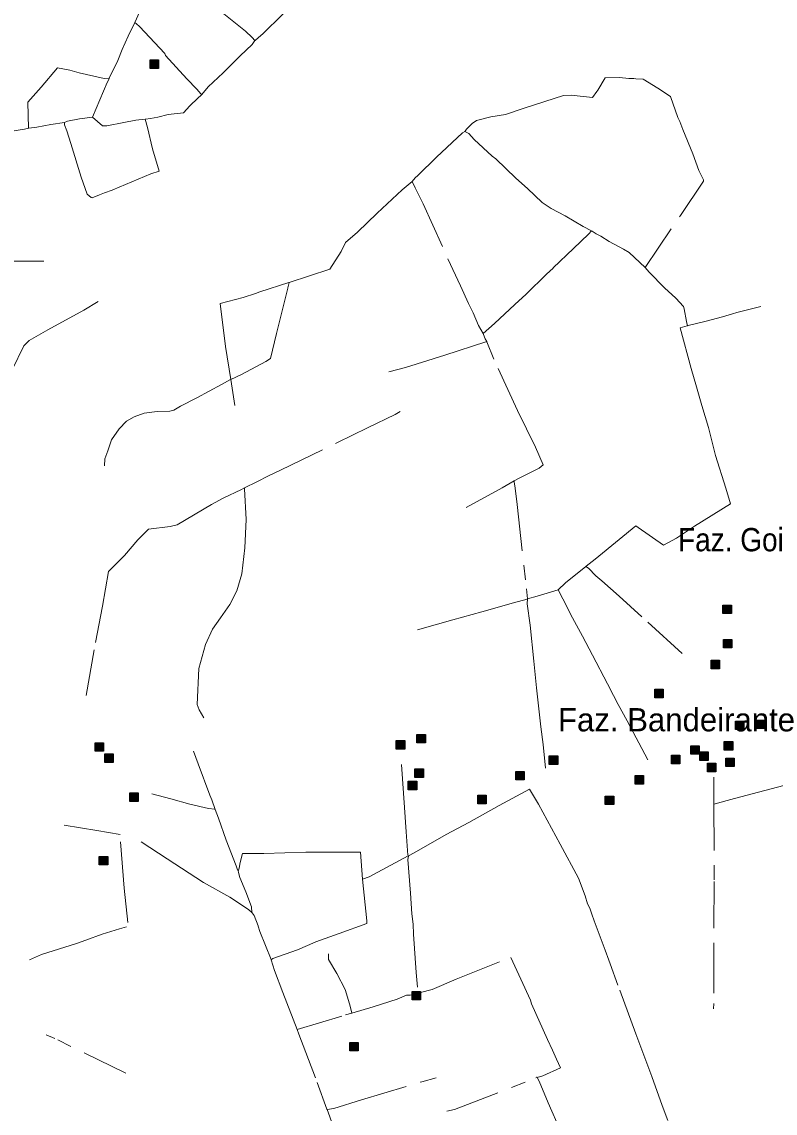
# Model space of a CAD drawing. Extents: x 393.5 to 446.9, y 8064.8 to 8120.4.
# Drawn here: x 407.05 to 412.23, y 8091.17 to 8098.67 of the extents above; entities that cross this region are included whole.
import ezdxf

# ---------------------------------------------------------------- set-up
doc = ezdxf.new("R2010")
doc.units = 0
doc.header["$LTSCALE"] = 0.064
doc.linetypes.add('DOT_DASHED', pattern=[7.7, 5, -1.2, 0.3, -1.2])
doc.layers.add('2', color=7, linetype='Continuous', lineweight=25)
doc.layers.add('22', color=7, linetype='DOT_DASHED', lineweight=13)
doc.layers.add('61', color=7, linetype='Continuous')

msp = doc.modelspace()

# ---------------------------------------------------------------- hatches: boundary and pattern name
at = {"layer": '2'}
for points in [[(407.936, 8098.4084), (407.994, 8098.4084), (407.994, 8098.3504), (407.936, 8098.3504)], [(411.8734, 8094.6626), (411.9314, 8094.6626), (411.9314, 8094.6046), (411.8734, 8094.6046)], [(411.8772, 8094.4259), (411.9352, 8094.4259), (411.9352, 8094.3679), (411.8772, 8094.3679)], [(411.7923, 8094.2825), (411.8503, 8094.2825), (411.8503, 8094.2245), (411.7923, 8094.2245)], [(411.4043, 8094.0837), (411.4623, 8094.0837), (411.4623, 8094.0257), (411.4043, 8094.0257)], [(411.96, 8093.8644), (412.018, 8093.8644), (412.018, 8093.8064), (411.96, 8093.8064)], [(412.1068, 8093.8715), (412.1648, 8093.8715), (412.1648, 8093.8135), (412.1068, 8093.8135)], [(407.5578, 8093.716), (407.6158, 8093.716), (407.6158, 8093.658), (407.5578, 8093.658)], [(409.6277, 8093.7308), (409.6857, 8093.7308), (409.6857, 8093.6728), (409.6277, 8093.6728)], [(409.77, 8093.7728), (409.828, 8093.7728), (409.828, 8093.7148), (409.77, 8093.7148)], [(411.883, 8093.7235), (411.941, 8093.7235), (411.941, 8093.6655), (411.883, 8093.6655)], [(407.6236, 8093.6388), (407.6816, 8093.6388), (407.6816, 8093.5808), (407.6236, 8093.5808)], [(410.6798, 8093.6257), (410.7378, 8093.6257), (410.7378, 8093.5677), (410.6798, 8093.5677)], [(411.5191, 8093.63), (411.5771, 8093.63), (411.5771, 8093.572), (411.5191, 8093.572)], [(411.6521, 8093.6952), (411.7101, 8093.6952), (411.7101, 8093.6372), (411.6521, 8093.6372)], [(411.7151, 8093.6529), (411.7731, 8093.6529), (411.7731, 8093.5949), (411.7151, 8093.5949)], [(411.7667, 8093.5746), (411.8247, 8093.5746), (411.8247, 8093.5166), (411.7667, 8093.5166)], [(411.8939, 8093.6104), (411.9519, 8093.6104), (411.9519, 8093.5524), (411.8939, 8093.5524)], [(409.7558, 8093.5363), (409.8138, 8093.5363), (409.8138, 8093.4783), (409.7558, 8093.4783)], [(410.4488, 8093.5188), (410.5068, 8093.5188), (410.5068, 8093.4608), (410.4488, 8093.4608)], [(411.2698, 8093.4904), (411.3278, 8093.4904), (411.3278, 8093.4324), (411.2698, 8093.4324)], [(409.71, 8093.4512), (409.768, 8093.4512), (409.768, 8093.3932), (409.71, 8093.3932)], [(407.7957, 8093.3708), (407.8537, 8093.3708), (407.8537, 8093.3128), (407.7957, 8093.3128)], [(410.1873, 8093.3551), (410.2453, 8093.3551), (410.2453, 8093.2971), (410.1873, 8093.2971)], [(411.0644, 8093.3499), (411.1224, 8093.3499), (411.1224, 8093.2919), (411.0644, 8093.2919)], [(407.5855, 8092.9343), (407.6435, 8092.9343), (407.6435, 8092.8763), (407.5855, 8092.8763)], [(409.7361, 8092.0072), (409.7941, 8092.0072), (409.7941, 8091.9492), (409.7361, 8091.9492)], [(409.3085, 8091.6564), (409.3665, 8091.6564), (409.3665, 8091.5984), (409.3085, 8091.5984)]]:
    msp.add_hatch(color=256, dxfattribs=at).paths.add_polyline_path(points)

# ---------------------------------------------------------------- linework, layer by layer
for points in [[(407.936, 8098.4084), (407.994, 8098.4084), (407.994, 8098.3504), (407.936, 8098.3504)], [(411.8734, 8094.6626), (411.9314, 8094.6626), (411.9314, 8094.6046), (411.8734, 8094.6046)], [(411.8772, 8094.4259), (411.9352, 8094.4259), (411.9352, 8094.3679), (411.8772, 8094.3679)], [(411.7923, 8094.2825), (411.8503, 8094.2825), (411.8503, 8094.2245), (411.7923, 8094.2245)], [(411.4043, 8094.0837), (411.4623, 8094.0837), (411.4623, 8094.0257), (411.4043, 8094.0257)], [(411.96, 8093.8644), (412.018, 8093.8644), (412.018, 8093.8064), (411.96, 8093.8064)], [(412.1068, 8093.8715), (412.1648, 8093.8715), (412.1648, 8093.8135), (412.1068, 8093.8135)], [(407.5578, 8093.716), (407.6158, 8093.716), (407.6158, 8093.658), (407.5578, 8093.658)], [(409.6277, 8093.7308), (409.6857, 8093.7308), (409.6857, 8093.6728), (409.6277, 8093.6728)], [(409.77, 8093.7728), (409.828, 8093.7728), (409.828, 8093.7148), (409.77, 8093.7148)], [(411.883, 8093.7235), (411.941, 8093.7235), (411.941, 8093.6655), (411.883, 8093.6655)], [(407.6236, 8093.6388), (407.6816, 8093.6388), (407.6816, 8093.5808), (407.6236, 8093.5808)], [(410.6798, 8093.6257), (410.7378, 8093.6257), (410.7378, 8093.5677), (410.6798, 8093.5677)], [(411.5191, 8093.63), (411.5771, 8093.63), (411.5771, 8093.572), (411.5191, 8093.572)], [(411.6521, 8093.6952), (411.7101, 8093.6952), (411.7101, 8093.6372), (411.6521, 8093.6372)], [(411.7151, 8093.6529), (411.7731, 8093.6529), (411.7731, 8093.5949), (411.7151, 8093.5949)], [(411.7667, 8093.5746), (411.8247, 8093.5746), (411.8247, 8093.5166), (411.7667, 8093.5166)], [(411.8939, 8093.6104), (411.9519, 8093.6104), (411.9519, 8093.5524), (411.8939, 8093.5524)], [(409.7558, 8093.5363), (409.8138, 8093.5363), (409.8138, 8093.4783), (409.7558, 8093.4783)], [(410.4488, 8093.5188), (410.5068, 8093.5188), (410.5068, 8093.4608), (410.4488, 8093.4608)], [(411.2698, 8093.4904), (411.3278, 8093.4904), (411.3278, 8093.4324), (411.2698, 8093.4324)], [(409.71, 8093.4512), (409.768, 8093.4512), (409.768, 8093.3932), (409.71, 8093.3932)], [(407.7957, 8093.3708), (407.8537, 8093.3708), (407.8537, 8093.3128), (407.7957, 8093.3128)], [(410.1873, 8093.3551), (410.2453, 8093.3551), (410.2453, 8093.2971), (410.1873, 8093.2971)], [(411.0644, 8093.3499), (411.1224, 8093.3499), (411.1224, 8093.2919), (411.0644, 8093.2919)], [(407.5855, 8092.9343), (407.6435, 8092.9343), (407.6435, 8092.8763), (407.5855, 8092.8763)], [(409.7361, 8092.0072), (409.7941, 8092.0072), (409.7941, 8091.9492), (409.7361, 8091.9492)], [(409.3085, 8091.6564), (409.3665, 8091.6564), (409.3665, 8091.5984), (409.3085, 8091.5984)]]:
    msp.add_lwpolyline(points, close=True, dxfattribs=at)
at = {"layer": '22'}
for p, q in [((407.83, 8098.6664), (407.8406, 8098.6558)), ((407.9006, 8098.0014), (407.9009, 8098.0004)), ((409.7368, 8097.5733), (409.7587, 8097.5284)), ((410.2254, 8096.5273), (410.2274, 8096.5223)), ((409.7746, 8094.4923), (410.0176, 8094.5617)), ((411.8111, 8093.4789), (411.8117, 8093.295)), ((408.383, 8093.2582), (408.4043, 8093.1987)), ((408.6781, 8092.4582), (408.6787, 8092.4564))]:
    msp.add_line(p, q, dxfattribs=at)
for points in [[(407.83, 8098.6664), (408.0233, 8099.0981), (408.0233, 8099.1098), (407.9602, 8099.1529), (407.7401, 8099.3272), (407.4951, 8099.5181), (407.4476, 8099.5602), (407.4457, 8099.5619), (407.4445, 8099.563)], [(408.7258, 8099.347), (408.6856, 8099.3121), (408.4969, 8099.1933), (408.2819, 8099.0588), (408.1823, 8098.989), (408.1631, 8098.9768), (408.1631, 8098.9576), (408.233, 8098.9052), (408.3728, 8098.7812), (408.5912, 8098.6066), (408.6367, 8098.5629), (408.6563, 8098.5415)], [(408.8535, 8099.1468), (408.8833, 8099.0981), (408.9462, 8099.0073), (409.0143, 8098.9025), (409.0004, 8098.878), (408.8448, 8098.7209), (408.7103, 8098.5882), (408.6808, 8098.5624), (408.6569, 8098.542), (408.6563, 8098.5415)], [(407.6545, 8098.282), (407.7122, 8098.4053), (407.7437, 8098.4799), (407.7854, 8098.5709), (407.83, 8098.6664)], [(407.8406, 8098.6558), (407.8618, 8098.6389), (408.036, 8098.4534), (408.041, 8098.4384)], [(408.2897, 8098.1701), (408.3333, 8098.2226), (408.4364, 8098.3204), (408.5552, 8098.4374), (408.6374, 8098.5142), (408.6563, 8098.5415)], [(408.041, 8098.4384), (408.1884, 8098.2782), (408.2553, 8098.2074), (408.2831, 8098.1756), (408.2897, 8098.1701)], [(407.3824, 8098.3373), (407.2988, 8098.354), (407.1865, 8098.2207), (407.0955, 8098.1191), (407.0988, 8097.9388)], [(407.6545, 8098.282), (407.6192, 8098.2808), (407.4464, 8098.319), (407.3824, 8098.3373)], [(407.5396, 8098.0158), (407.6396, 8098.2524), (407.6528, 8098.2786), (407.6545, 8098.282)], [(411.2607, 8098.2802), (411.2276, 8098.2798), (411.1628, 8098.2882), (411.0643, 8098.2854), (411.0139, 8098.2008)], [(411.3388, 8096.9823), (411.5824, 8097.3404), (411.7394, 8097.5746), (411.7394, 8097.5844), (411.7084, 8097.6491), (411.6662, 8097.7631), (411.5979, 8097.9304), (411.5768, 8097.9853), (411.5631, 8098.0139), (411.5121, 8098.1576), (411.4262, 8098.2153), (411.3263, 8098.2757), (411.2756, 8098.2786), (411.2607, 8098.2802)], [(411.0139, 8098.2008), (411.0066, 8098.1912), (410.977, 8098.1504), (410.8292, 8098.1658), (410.7779, 8098.1631), (410.7131, 8098.1434), (410.5076, 8098.0773), (410.3781, 8098.0337), (410.2781, 8098.0168), (410.1796, 8097.9929), (410.1488, 8097.9709), (410.1108, 8097.9315), (410.1002, 8097.9183), (410.0995, 8097.9174)], [(408.2857, 8098.1653), (408.2623, 8098.1445), (408.2082, 8098.0922), (408.1645, 8098.045), (408.0596, 8098.0328), (407.988, 8098.0153), (407.939, 8098.0066), (407.904, 8098.0019), (407.9006, 8098.0014)], [(408.2857, 8098.1653), (408.2862, 8098.166), (408.2886, 8098.1688), (408.2894, 8098.1698), (408.2897, 8098.1701)], [(407.3458, 8097.9777), (407.2526, 8097.9658), (407.1572, 8097.9459), (407.1024, 8097.9392), (407.0988, 8097.9388)], [(407.5396, 8098.0158), (407.4504, 8098.0036), (407.3666, 8097.9872), (407.3458, 8097.9777)], [(407.6733, 8097.5134), (407.6215, 8097.4942), (407.5883, 8097.4803), (407.5359, 8097.461), (407.5306, 8097.4628), (407.5024, 8097.4855), (407.4622, 8097.6025), (407.3906, 8097.833), (407.3626, 8097.9203), (407.3473, 8097.9617), (407.3458, 8097.9777)], [(407.9006, 8098.0014), (407.8367, 8097.9949), (407.7545, 8097.9792), (407.6374, 8097.9565), (407.6077, 8097.9547), (407.5396, 8098.0158)], [(407.9009, 8098.0004), (407.918, 8097.9447), (407.951, 8097.7984), (407.9983, 8097.6451), (407.9392, 8097.6262), (407.6794, 8097.5157), (407.6733, 8097.5134)], [(406.1156, 8097.7635), (406.1421, 8097.7641), (406.2791, 8097.7908), (406.5127, 8097.832), (406.6751, 8097.8605), (406.7514, 8097.8762), (406.839, 8097.8918), (406.9701, 8097.916), (407.0726, 8097.9331), (407.0988, 8097.9388)], [(410.0995, 8097.9174), (410.0833, 8097.9063), (409.9046, 8097.7403), (409.775, 8097.6151), (409.7579, 8097.5972), (409.7368, 8097.5733)], [(410.0995, 8097.9174), (410.1263, 8097.9019), (410.1638, 8097.8608), (410.2863, 8097.7461), (410.3118, 8097.7281)], [(410.3118, 8097.7281), (410.4502, 8097.5969), (410.5306, 8097.5252), (410.6314, 8097.4283), (410.6922, 8097.3864), (410.7892, 8097.337), (410.9128, 8097.2629), (410.9689, 8097.2343)], [(408.8923, 8096.8795), (409.1709, 8096.9713), (409.2497, 8097.0909), (409.2786, 8097.1541), (409.3616, 8097.2245), (409.4968, 8097.3553), (409.6692, 8097.5156), (409.7362, 8097.5728), (409.7368, 8097.5733)], [(409.7587, 8097.5284), (409.8131, 8097.4187), (409.9827, 8097.0417), (410.0702, 8096.8555), (410.1253, 8096.7357), (410.1557, 8096.6711), (410.1919, 8096.5837), (410.2254, 8096.5273)], [(410.7053, 8096.9776), (410.7072, 8096.9793), (410.8467, 8097.1126), (410.949, 8097.2116), (410.9689, 8097.2343)], [(411.3388, 8096.9823), (411.2288, 8097.0848), (411.1908, 8097.1073), (411.0922, 8097.1608), (411.0331, 8097.1974), (411.0024, 8097.2126), (410.9745, 8097.2307), (410.9689, 8097.2343)], [(406.9634, 8097.0253), (407.0455, 8097.025), (407.2036, 8097.0264)], [(410.2254, 8096.5273), (410.3041, 8096.597), (410.4429, 8096.7281), (410.5209, 8096.7985), (410.6597, 8096.9372), (410.7053, 8096.9776)], [(411.3388, 8096.9823), (411.3662, 8096.949), (411.4727, 8096.8426), (411.5488, 8096.7704), (411.6021, 8096.7133), (411.6078, 8096.6981), (411.6227, 8096.6107), (411.6299, 8096.5815)], [(408.4896, 8096.2125), (408.5642, 8096.2477), (408.7317, 8096.3349), (408.7618, 8096.3571), (408.8038, 8096.5294), (408.8818, 8096.8428), (408.8923, 8096.8795)], [(408.8923, 8096.8795), (408.8882, 8096.8782), (408.6891, 8096.8145)], [(408.6891, 8096.8145), (408.6598, 8096.8024), (408.5753, 8096.7757), (408.4163, 8096.7335), (408.4533, 8096.4381), (408.4896, 8096.2125)], [(406.8717, 8096.0305), (406.8807, 8096.0507), (406.956, 8096.2069), (406.9879, 8096.2797), (407.0671, 8096.443), (407.1026, 8096.4806), (407.2329, 8096.5534), (407.4794, 8096.6886), (407.5786, 8096.7482)], [(411.9388, 8096.664), (411.97, 8096.6723), (412.1333, 8096.7145)], [(411.6259, 8096.5807), (411.7577, 8096.6129), (411.8717, 8096.6424), (411.9388, 8096.664)], [(411.464, 8095.0739), (411.5552, 8095.1224), (411.6791, 8095.2054), (411.9262, 8095.3587), (411.8938, 8095.4656), (411.8227, 8095.6907), (411.7742, 8095.882), (411.7284, 8096.034), (411.691, 8096.1619), (411.6544, 8096.2885), (411.579, 8096.5671), (411.6278, 8096.5809), (411.6299, 8096.5815)], [(410.2274, 8096.5223), (410.2395, 8096.4926), (410.2503, 8096.4725)], [(409.5758, 8096.264), (409.69, 8096.2956), (409.9623, 8096.3806), (410.2444, 8096.4706), (410.245, 8096.4708), (410.2503, 8096.4725)], [(410.4381, 8095.515), (410.4772, 8095.5374), (410.6104, 8095.6039), (410.637, 8095.6248), (410.5838, 8095.7477), (410.4621, 8095.9985), (410.2976, 8096.352), (410.2512, 8096.4702), (410.2503, 8096.4725)], [(407.644, 8095.7214), (407.6694, 8095.7974), (407.7229, 8095.8734), (407.7736, 8095.9268), (407.8256, 8095.955), (407.8953, 8095.9816), (407.9826, 8095.9915), (408.0713, 8095.9943), (408.0981, 8096.0013), (408.1445, 8096.028), (408.2557, 8096.0857), (408.4269, 8096.1772), (408.4889, 8096.2121), (408.4896, 8096.2125)], [(408.5174, 8096.034), (408.4898, 8096.2115), (408.4896, 8096.2125)], [(408.5847, 8095.4676), (408.6683, 8095.5085), (408.7501, 8095.5503), (408.8319, 8095.5883), (409.2235, 8095.7799), (409.4308, 8095.8807), (409.6191, 8095.9719), (409.6552, 8095.9928)], [(407.6215, 8095.6201), (407.6229, 8095.6666), (407.644, 8095.7214)], [(410.1083, 8095.3336), (410.3555, 8095.4671), (410.4377, 8095.5148), (410.4381, 8095.515)], [(410.4381, 8095.515), (410.4383, 8095.5136), (410.439, 8095.5086), (410.4449, 8095.4648)], [(407.4954, 8094.0406), (407.5601, 8094.4051), (407.6084, 8094.6549), (407.6491, 8094.8936), (407.7585, 8095.0039), (407.8517, 8095.1103), (407.9239, 8095.1844), (408.0742, 8095.2015), (408.1217, 8095.2129), (408.3584, 8095.3536), (408.4383, 8095.3973), (408.5638, 8095.4562), (408.5805, 8095.4653), (408.5847, 8095.4676)], [(408.3041, 8093.8879), (408.2727, 8093.9418), (408.2594, 8093.9798), (408.2708, 8094.2269), (408.3165, 8094.3903), (408.365, 8094.4967), (408.4183, 8094.5746), (408.483, 8094.6658), (408.5305, 8094.7608), (408.5656, 8094.8768), (408.5866, 8095.0554), (408.5951, 8095.2493), (408.585, 8095.4611), (408.5847, 8095.4676)], [(410.4449, 8095.4648), (410.4582, 8095.3535), (410.5229, 8094.7734), (410.5302, 8094.7044), (410.5302, 8094.7041)], [(410.9332, 8094.9285), (410.9952, 8094.9782), (411.1599, 8095.1119), (411.2739, 8095.2061), (411.2908, 8095.1963), (411.464, 8095.0739)], [(410.7397, 8094.7662), (410.7903, 8094.815), (410.9318, 8094.9274), (410.9332, 8094.9285)], [(411.5942, 8094.3296), (411.3168, 8094.5814), (411.1592, 8094.7235), (411.0416, 8094.829), (410.9994, 8094.8641), (410.9487, 8094.9148), (410.9318, 8094.9274)], [(410.7397, 8094.7662), (410.597, 8094.7224), (410.5302, 8094.7041)], [(411.3583, 8093.5996), (411.2149, 8093.8662), (411.1527, 8093.9794), (411.1217, 8094.0415), (411.08, 8094.1204), (410.9758, 8094.3177), (410.9082, 8094.4491), (410.8259, 8094.5989), (410.8047, 8094.6432), (410.7397, 8094.7662)], [(410.0176, 8094.5617), (410.2168, 8094.6165), (410.4343, 8094.6768), (410.5277, 8094.7034), (410.5302, 8094.7041)], [(410.6538, 8093.5412), (410.6369, 8093.704), (410.6206, 8093.8258), (410.5914, 8094.0942), (410.574, 8094.2768), (410.5476, 8094.5252), (410.5284, 8094.6713), (410.5302, 8094.704), (410.5302, 8094.7041)], [(408.2337, 8093.6574), (408.2656, 8093.5714), (408.346, 8093.3566), (408.3599, 8093.3248), (408.383, 8093.2582)], [(409.6642, 8093.5668), (409.6849, 8093.2713), (409.6966, 8093.1034), (409.7072, 8092.9446)], [(411.8118, 8093.295), (411.9529, 8093.3336), (412.2047, 8093.3993), (412.3893, 8093.4476), (412.4566, 8093.4669), (412.4819, 8093.4728)], [(407.9466, 8093.365), (408.077, 8093.3317), (408.2087, 8093.2943), (408.3377, 8093.2652), (408.3812, 8093.2585), (408.383, 8093.2582)], [(410.9527, 8092.5935), (410.943, 8092.6091), (410.9256, 8092.6632), (410.8813, 8092.7865), (410.7543, 8093.0193), (410.6052, 8093.2951), (410.5442, 8093.3976), (410.3354, 8093.2854), (410.1274, 8093.169), (409.9706, 8093.0859), (409.7511, 8092.9592), (409.7122, 8092.9397)], [(411.8117, 8093.295), (411.8137, 8092.7616), (411.8107, 8092.3147), (411.8106, 8091.9237), (411.8076, 8091.8878)], [(408.4043, 8093.1987), (408.4589, 8093.0472), (408.5264, 8092.87), (408.5369, 8092.842), (408.5416, 8092.833)], [(407.7828, 8092.48), (407.7562, 8092.7171), (407.7287, 8093.0847), (407.5697, 8093.1136), (407.3433, 8093.1497)], [(407.8745, 8093.0356), (408.0518, 8092.918), (408.3024, 8092.7567), (408.483, 8092.6556), (408.6108, 8092.5695), (408.6357, 8092.5501)], [(409.3963, 8092.7784), (409.3807, 8092.9647), (409.2781, 8092.9647), (409.0062, 8092.9633), (408.7171, 8092.955), (408.5693, 8092.955), (408.5555, 8092.894), (408.5472, 8092.8538), (408.5416, 8092.833)], [(409.3963, 8092.7784), (409.4404, 8092.7942), (409.7089, 8092.938), (409.7105, 8092.9388), (409.7122, 8092.9397)], [(409.7352, 8092.5395), (409.725, 8092.6823), (409.708, 8092.9147), (409.7118, 8092.9375), (409.7122, 8092.9397)], [(408.5416, 8092.833), (408.5424, 8092.8297), (408.5427, 8092.8287), (408.5439, 8092.8239)], [(408.5439, 8092.8239), (408.5527, 8092.79), (408.5938, 8092.6923), (408.6316, 8092.5876), (408.6357, 8092.5501)], [(409.3963, 8092.7784), (409.4258, 8092.4933), (409.4258, 8092.4739), (409.2358, 8092.406), (409.0735, 8092.3474), (409.0708, 8092.3464)], [(411.0901, 8092.2213), (411.0634, 8092.2897), (410.9885, 8092.492), (410.9719, 8092.5391), (410.9604, 8092.5725), (410.9527, 8092.5935)], [(408.6781, 8092.4582), (408.651, 8092.528), (408.6371, 8092.5481), (408.6357, 8092.5501)], [(409.7737, 8092.0373), (409.7648, 8092.1375), (409.7454, 8092.4008), (409.744, 8092.4687), (409.7352, 8092.5395)], [(407.1062, 8092.2245), (407.1881, 8092.2606), (407.429, 8092.3376), (407.4941, 8092.3593), (407.6049, 8092.4002), (407.7256, 8092.4367), (407.7725, 8092.4509)], [(408.6787, 8092.4564), (408.6902, 8092.4197), (408.7669, 8092.2259), (408.7675, 8092.2245)], [(409.0708, 8092.3464), (408.9487, 8092.2937), (408.7795, 8092.2328), (408.7675, 8092.2245)], [(408.9469, 8091.7446), (408.8484, 8092.0001), (408.7897, 8092.1517), (408.7675, 8092.2245)], [(409.1606, 8092.2658), (409.1625, 8092.226), (409.2194, 8092.1294), (409.2763, 8092.0195), (409.3066, 8091.9229), (409.3213, 8091.859), (409.3217, 8091.857), (409.3218, 8091.8566)], [(409.6978, 8091.9807), (409.7227, 8091.9805), (409.8742, 8092.0213), (410.0401, 8092.091), (410.415, 8092.2408), (410.4836, 8092.0904), (410.5494, 8091.9463)], [(411.4944, 8091.1192), (411.4547, 8091.2224), (411.3843, 8091.4219), (411.2754, 8091.7165), (411.152, 8092.0494), (411.0979, 8092.1963), (411.0901, 8092.2213)], [(409.6978, 8091.9807), (409.6327, 8091.9532), (409.4677, 8091.9002), (409.3218, 8091.8566)], [(410.5494, 8091.9463), (410.5568, 8091.9208), (410.6678, 8091.6769), (410.7021, 8091.6033)], [(408.9469, 8091.7446), (409.2782, 8091.8452), (409.3218, 8091.8566)], [(407.768, 8091.4445), (407.2806, 8091.6839), (407.2202, 8091.7096)], [(408.9469, 8091.7446), (408.9584, 8091.7135), (409.0841, 8091.381), (409.1508, 8091.1982)], [(410.7021, 8091.6033), (410.7299, 8091.5412), (410.7563, 8091.4811), (410.6351, 8091.4278), (410.597, 8091.4166)], [(409.1519, 8091.1952), (409.1986, 8091.2026), (409.3882, 8091.2632), (409.8034, 8091.3863), (409.9018, 8091.4127)], [(409.9759, 8091.1835), (410.0285, 8091.1959), (410.5882, 8091.4122), (410.5936, 8091.4149), (410.597, 8091.4166)], [(410.7558, 8091.0482), (410.6715, 8091.2422), (410.61, 8091.3902), (410.5998, 8091.4109), (410.5974, 8091.4159), (410.597, 8091.4166), (410.5952, 8091.4203)], [(409.1508, 8091.1982), (409.1519, 8091.1952), (409.2382, 8090.9573), (409.2667, 8090.8769)]]:
    msp.add_lwpolyline(points, dxfattribs=at)

# ---------------------------------------------------------------- texts
at = {"layer": '61', "width": 0.9}
msp.add_text('Faz. Goiana', height=0.16, dxfattribs=at).set_placement((411.5647, 8095.0317))
at = {"layer": '61'}
msp.add_text('Faz. Bandeirante', height=0.16, dxfattribs=at).set_placement((410.7398, 8093.7942))

doc.saveas('drawing.dxf')
